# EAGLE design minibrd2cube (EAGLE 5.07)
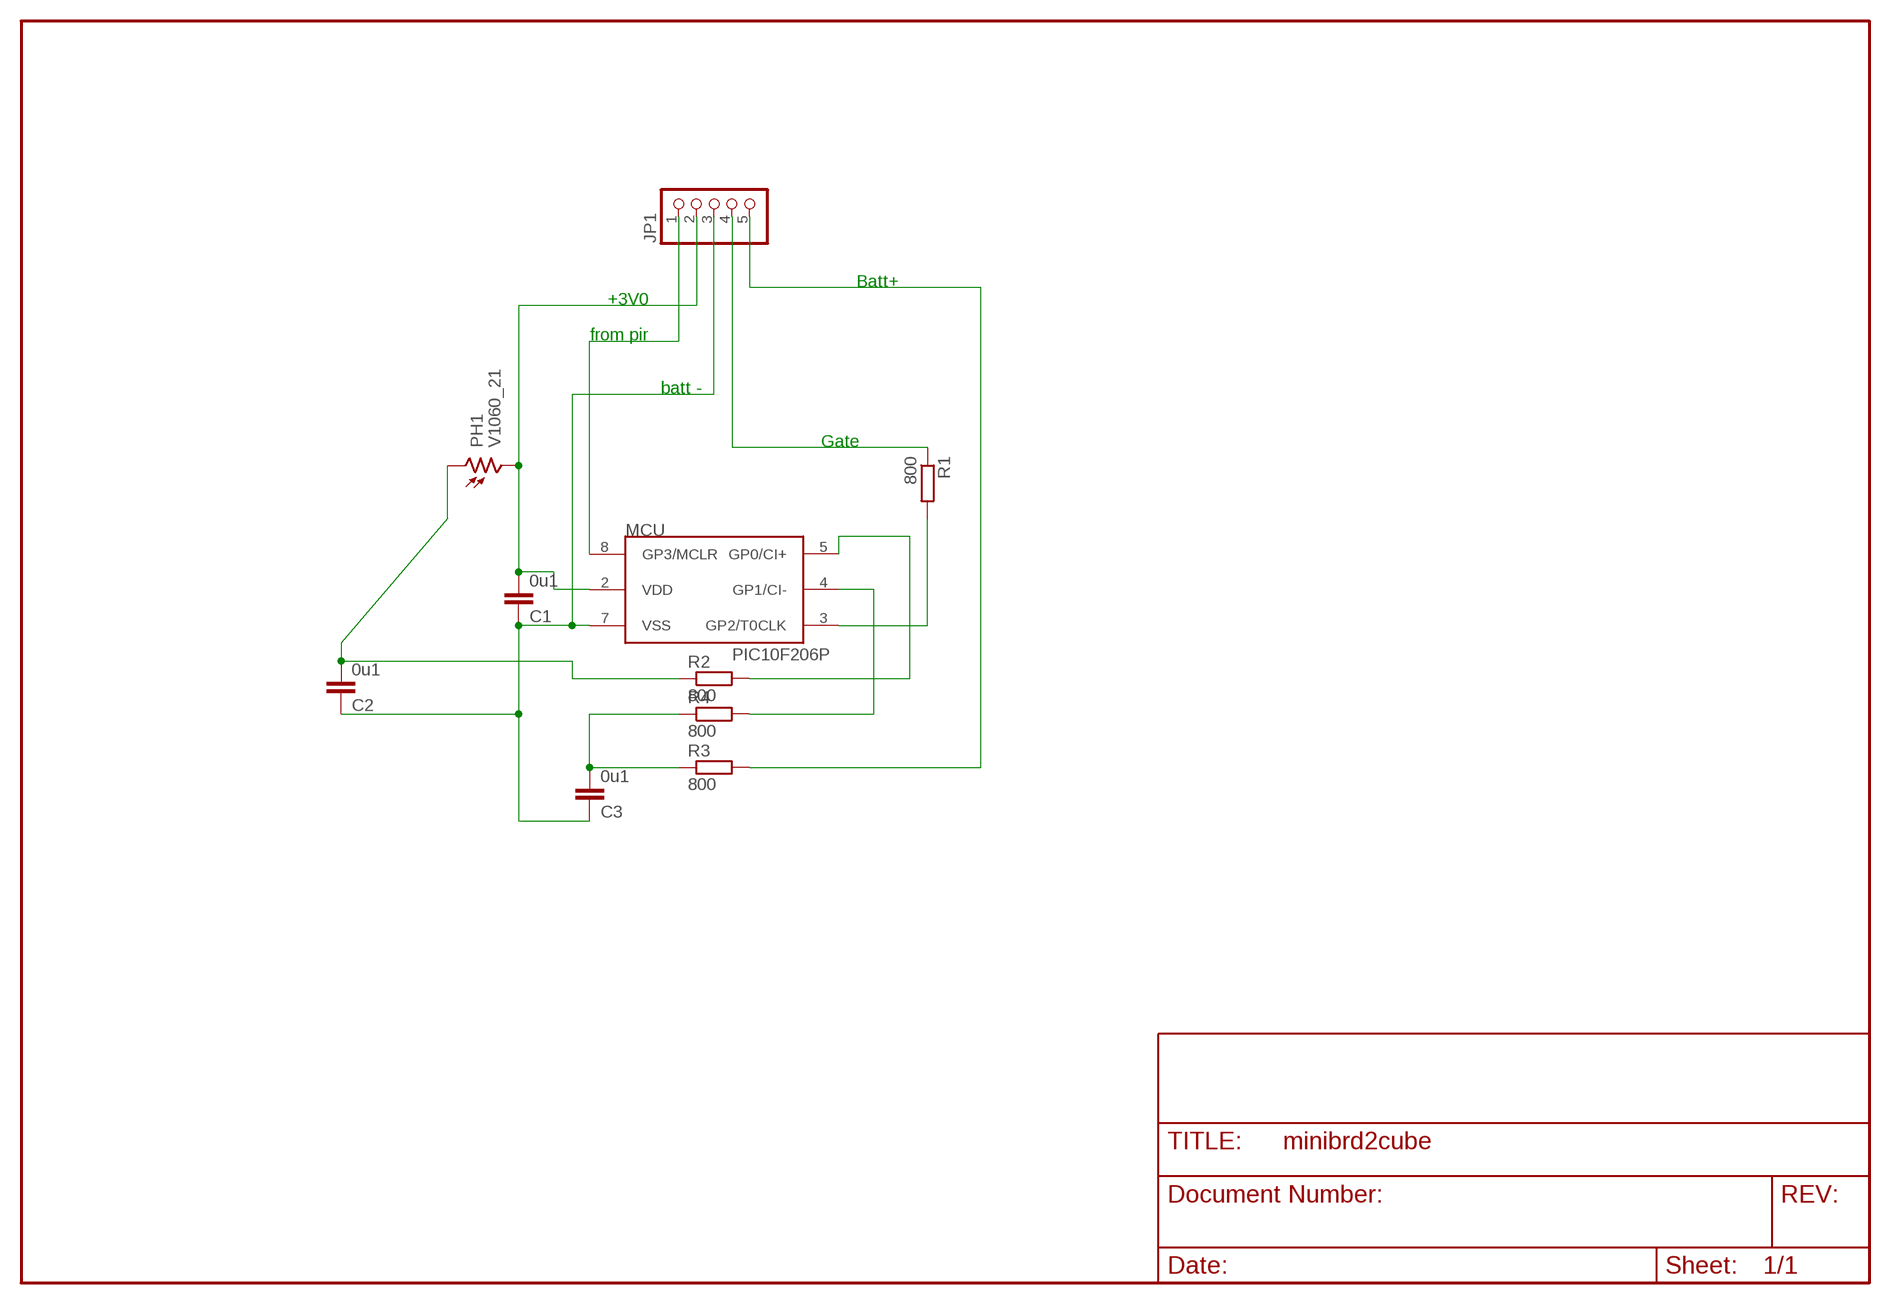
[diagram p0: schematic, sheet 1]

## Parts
C1  0u1  C-EUC1206  [C1206]
C2  0u1  C-EUC1206  [C1206]
C3  0u1  C-EUC1206  [C1206]
JP1  PINHD-1X5  [1X05]
MCU  PIC10F206P  [DIL8]
PH1  V1060_21  [TO-5_V10]
R1  800  R-EU_R1206  [R1206]
R2  800  R-EU_R1206  [R1206]
R3  800  R-EU_R1206  [R1206]
R4  800  R-EU_R1206  [R1206]

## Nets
GATE: JP1.4 R1.1
N$1: C2.2 PH1.1 R2.1
N$4: MCU.5(GP0/CI+) R2.2
N$5: MCU.3(GP2/T0CLK) R1.2
N$7: C3.2 R3.1 R4.1
N$8: MCU.4(GP1/CI-) R4.2
PIR: JP1.1 MCU.8(GP3/MCLR)
V3: C1.2 JP1.2 MCU.2(VDD) PH1.2
V+: JP1.5 R3.2
V-: C1.1 C2.1 C3.1 JP1.3 MCU.7(VSS)

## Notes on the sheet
- Batt+
- +3V0
- from pir
- batt -
- Gate

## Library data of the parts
C1-C3 = rcl:C-EU: CAPACITOR, European symbol
JP1 = pinhead:PINHD-1X5: PIN HEADER
MCU = microchip-3:PIC10F2*: uPC nW 0,25/0,5k Program Flash memory Comparator
PH1 = photo-elements:?1060*: Sensor Street Light control
R1-R4 = rcl:R-EU_: RESISTOR, European symbol

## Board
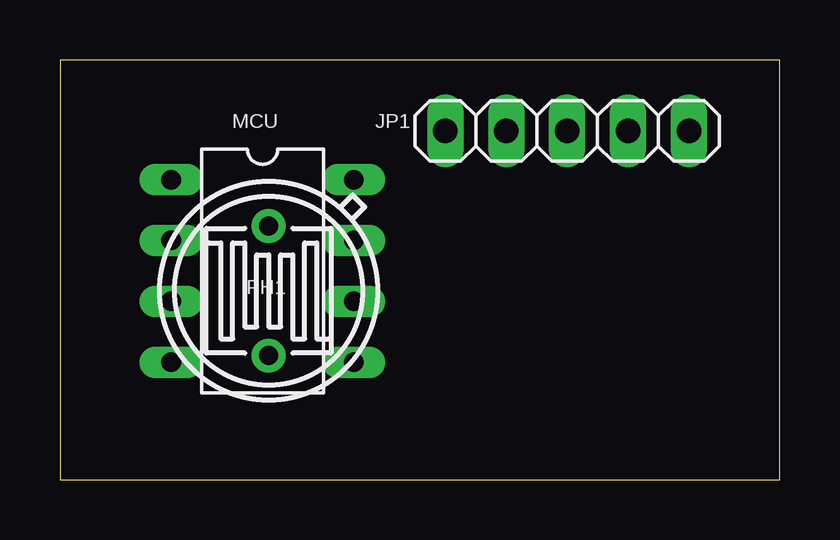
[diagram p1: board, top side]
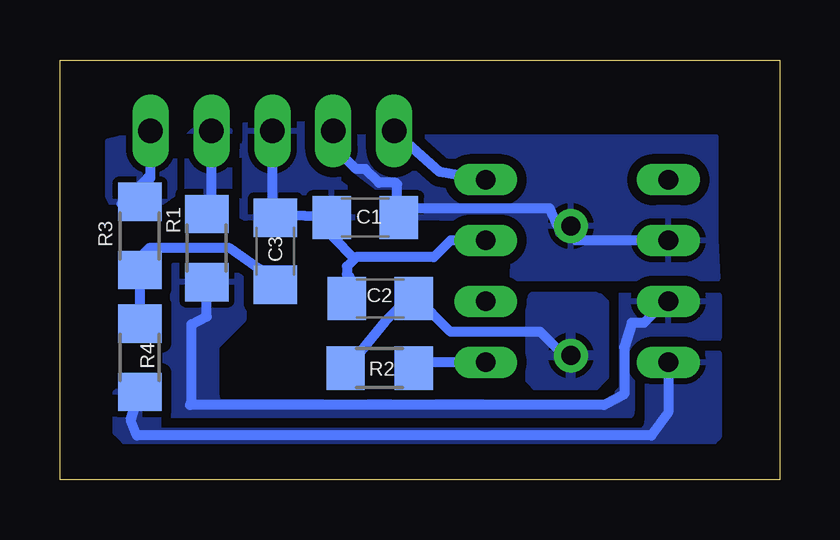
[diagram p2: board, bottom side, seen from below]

Size 30 x 17.5 mm. Coordinates in mm from the lower left corner, seen from the top.
Outline: 0,0 30,0 30,17.5 0,17.5 0,0
Copper layers (1*16): Top 0.035mm / dielectric 1.5mm / Bottom 0.035mm
Design rules "default": minimum track width 10mil, minimum drill 24mil, track to track 8mil, track to pad 8mil, pad to pad 8mil, via to via 8mil, smd to smd 8mil, copper to edge 1mil, drill to drill 8mil, minimum pad ring 10mil, minimum via ring 8mil, stop-mask expansion 4mil, vias tented up to drill 0mil, thermal gap 10mil

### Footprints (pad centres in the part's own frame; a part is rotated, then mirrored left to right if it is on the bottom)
C1206 = smd 1.6 x 1.8: 1 -1.4,0; 2 1.4,0
1X05 = drill 1.016 long: 1 -5.08,0; 2 -2.54,0; 3 0,0; 4 2.54,0; 5 5.08,0
DIL8 = drill 0.813 long: 1 -3.81,-3.81; 2 -1.27,-3.81; 3 1.27,-3.81; 4 3.81,-3.81; 5 3.81,3.81; 6 1.27,3.81; 7 -1.27,3.81; 8 -3.81,3.81
TO-5_V10 = drill 0.8 pad 1.4 round: 1 -2.7,0; 2 2.7,0
R1206 = smd 1.6 x 1.803: 1 -1.422,0; 2 1.422,0

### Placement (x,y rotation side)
C1  17.27,10.92 0 bottom
C2  16.65,7.55 0 bottom
C3  21.02,9.53 270 bottom
JP1  21.15,14.54 0 top
MCU  8.45,8.7 270 top
PH1  8.7,7.87 90 top
R1  23.88,9.65 270 bottom
R2  16.67,4.65 0 bottom
R3  26.67,10.16 90 bottom
R4  26.67,5.08 270 bottom

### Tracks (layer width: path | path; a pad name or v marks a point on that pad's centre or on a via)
GATE
  Bottom 0.406: 23.91,11.07 24.07,10.92 | 23.91,11.07 R1.1 23.88,11.24 23.69,11.43 JP1.4 | 23.91,11.07 23.69,11.3
  pour Bottom (isolate 0.406): 22.92,14.54 24.45,14.54 24.7,14.29 24.7,11.94 24.77,11.87 23.24,11.87 22.92,12.13
N$1
  Bottom 0.406: 9.02,5.21 9.97,6.16 13.72,6.16 15.19,7.63 C2.2 15.74,7.31 16.45,6.6 18.02,4.65 R2.1
  pour Bottom (isolate 0.406): 7.68,7.62 10.29,7.62 10.41,7.37 10.41,4.19 10.03,3.81 7.81,3.81 7.3,4.32 7.3,7.37 7.49,7.56
N$4
  Bottom 0.406: 15.36,4.78 15.37,4.76 | 15.36,4.78 R2.2 | MCU.5 15.24,4.89 15.36,4.78
N$5
  Bottom 0.406: R1.2 23.88,6.79 24.51,6.48 24.51,3.3 24.57,3.11 7.3,3.11 6.48,3.56 6.48,5.52 6.16,6.54 5.65,6.54 4.76,7.43 MCU.3
  pour Bottom (isolate 0.406, rank 2): 2.54,7.68 2.54,5.91 5.08,5.91 6.16,4.83 6.16,2.86 6.22,2.67 25.34,2.67 25.59,2.98 25.59,8.45 25.08,9.14 22.48,9.14 22.35,9.02 22.35,6.67 23.5,5.52 23.5,3.56 23.43,3.24 12.38,3.24 7.75,3.11 6.73,3.49 6.73,7.68
N$7
  Bottom 0.406: C3.2 21.65,8.76 22.92,9.65 26.29,9.65 26.95,8.99 R3.1 R4.1
N$8
  Bottom 0.406: R4.2 27.05,2.48 26.8,1.84 5.33,1.84 4.64,2.79 4.64,4.7 4.76,4.83 4.7,4.89 MCU.4
  pour Bottom (isolate 0.406, rank 3): 2.54,5.27 2.54,1.78 2.73,1.59 27.3,1.59 27.69,1.97 27.69,3.62 27.43,3.87 26.23,3.87 25.78,3.43 25.78,2.92 25.53,2.67 6.03,2.67 5.97,2.73 5.97,4.89 5.59,5.27
PIR
  Bottom 0.406: MCU.8 12.32,12.51 14.16,12.83 JP1.1
V3
  Bottom 0.406: MCU.2 8.51,9.97 | 9.14,10.29 9.59,11.3 15.56,11.3 | 15.88,11.04 15.94,10.99 | 15.88,11.04 C1.2 | 15.56,11.3 15.88,11.04 | JP1.2 18.61,13.91 17.65,12.95 17.27,12.95 16.7,12.38 16,12.38 15.94,12.32 15.94,11.68 15.56,11.3
  pour Bottom (isolate 0.406): 2.67,14.29 2.67,10.03 2.6,8.38 11.11,8.38 11.05,10.86 15.75,10.92 16.26,10.86 16.64,12.06 19.11,13.97 19.11,14.1 18.92,14.29
V+
  Bottom 0.406: 26.35,12.57 27.43,11.49 27.37,11.49 27.05,11.81 R3.2 | 26.35,12.57 26.23,12.7 | 26.35,12.57 26.29,12.51 26.23,12.57 JP1.5
  pour Bottom (isolate 0.406): 25.21,14.29 27.5,14.22 28,14.1 28,11.81 27.88,11.56 25.78,11.56 25.21,11.94
V-
  Bottom 0.406: JP1.3 21.14,11.3 20.64,10.79 C3.1 20.63,10.93 20.51,11.05 20.5,11.04 C1.1 18.6,10.1 17.72,9.21 | MCU.7 13.72,9.97 14.41,9.27 17.65,9.27 17.72,9.21 | 17.72,9.21 18.03,8.89 18.03,8.57 17.91,8.45 17.96,8.39 C2.1
  pour Bottom (isolate 0.406, rank 2): 19.75,14.8 22.29,14.8 22.42,14.67 22.42,10.99 21.53,10.41 17.78,10.41 17.84,12.32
